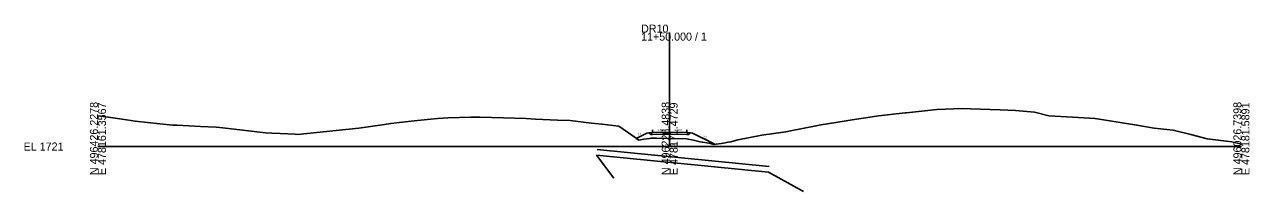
# Model space of a CAD drawing. Extents: x -26 to 403, y -10 to 2062.
# Drawn here: x -25.7 to 402.8, y 1484.3 to 1542.7 of the extents above; entities that cross this region are included whole.
import ezdxf

# ---------------------------------------------------------------- set-up
doc = ezdxf.new("R2010")
doc.units = 0
for name, color, linetype in [('Exist Cross Section Cell', 7, 'Continuous'), ('Exist XS Center Line Elevation Label', 7, 'Continuous'), ('Exist XS Ground Line', 7, 'Continuous'), ('Prop XS Dump Level', 7, 'Continuous'), ('Prop XS Earthwork Shape', 7, 'Continuous'), ('Prop XS EOT Tick Mark', 7, 'Continuous'), ('Prop XS Finish Grade', 7, 'Continuous'), ('Prop XS Finish Grade Earthwork', 7, 'Continuous'), ('Prop XS Finish Grade Pavement', 7, 'Continuous'), ('Prop XS Pvmt Edge Slope', 7, 'Continuous'), ('Prop XS SE Text', 7, 'Continuous'), ('Prop XS Shoulder Borrow Shape', 7, 'Continuous'), ('Prop XS Side Slope Text', 7, 'Continuous'), ('Prop XS Subgrade Earthwork', 7, 'Continuous'), ('Scratch_Level_5', 7, 'Continuous'), ('Scratch_Level_9', 7, 'Continuous')]:
    doc.layers.add(name, color=color, linetype=linetype)

msp = doc.modelspace()

# ---------------------------------------------------------------- linework, layer by layer
at = {"layer": 'Exist Cross Section Cell'}
for p, q in [((200, 1500), (200, 1539.86)), ((0, 1500), (200, 1500)), ((200, 1500), (400, 1500))]:
    msp.add_line(p, q, dxfattribs=at)
at = {"layer": 'Exist XS Ground Line'}
msp.add_lwpolyline([(0, 1510.79), (2.76, 1510.38), (8.44, 1509.55), (13.04, 1508.93), (21.7, 1507.93), (26.15, 1507.53), (27.71, 1507.42), (35.91, 1507.05), (41.41, 1506.75), (42.62, 1506.65), (56.67, 1504.97), (58.67, 1504.77), (60.82, 1504.72), (63.73, 1504.58), (68.95, 1504.33), (69.8, 1504.26), (83.31, 1505.55), (91.28, 1506.39), (100.24, 1507.69), (102.5, 1508.07), (110.61, 1508.99), (118.79, 1509.78), (122.39, 1510.06), (130.46, 1510.25), (133.63, 1510.25), (141.88, 1510.06), (149.65, 1509.75), (153.05, 1509.63), (160.78, 1509.27), (165.2, 1509.08), (172.63, 1508.2), (176.25, 1507.82), (182.27, 1507.16), (188.28, 1502.87), (189.27, 1502.24), (191.01, 1502.54), (192.97, 1502.8), (193.51, 1502.87), (195.4, 1502.88), (200, 1502.78), (205.84, 1502.65), (208.39, 1502.18), (210.72, 1501.61), (213.87, 1501.13), (215.45, 1500.76), (218.86, 1501.21), (220.45, 1501.54), (221.37, 1501.68), (223.83, 1502.29), (232.29, 1503.98), (240.66, 1505.18), (242.3, 1505.44), (251.21, 1507.29), (252.32, 1507.5), (261.76, 1508.98), (262.33, 1509.1), (272.35, 1510.68), (273.05, 1510.76), (282.36, 1511.76), (282.86, 1511.8), (292.38, 1512.88), (293.41, 1512.95), (302.39, 1513.29), (305.21, 1513.18), (315.63, 1512.85), (320.99, 1512.63), (327.6, 1512.06), (332.65, 1510.74), (340.94, 1510.33), (348.82, 1509.8), (355.4, 1508.78), (362.69, 1507.63), (369.52, 1506.46), (376.14, 1505.67), (382.31, 1504.2), (388.04, 1502.73), (396.65, 1501.66), (400, 1500.78)], dxfattribs=at)
at = {"layer": 'Prop XS Dump Level'}
for p, q in [((200, 1504.97), (194, 1504.85)), ((206, 1504.85), (200, 1504.97))]:
    msp.add_line(p, q, dxfattribs=at)
at = {"layer": 'Prop XS Earthwork Shape'}
msp.add_lwpolyline([(200, 1504.3), (194, 1504.18), (193.32, 1504.17), (192.74, 1504.75), (192, 1504.69), (188.32, 1502.85), (189.27, 1502.24), (191.01, 1502.54), (192.97, 1502.8), (193.51, 1502.87), (195.4, 1502.88), (200, 1502.78), (205.84, 1502.65), (208.39, 1502.18), (210.72, 1501.61), (213.87, 1501.13), (215.45, 1500.76), (215.77, 1500.8), (208, 1504.69), (207.26, 1504.75), (206.68, 1504.17), (206, 1504.18)], close=True, dxfattribs=at)
at = {"layer": 'Prop XS EOT Tick Mark'}
for p, q in [((194, 1504.85), (194, 1505.85)), ((206, 1504.85), (206, 1505.85))]:
    msp.add_line(p, q, dxfattribs=at)
at = {"layer": 'Prop XS Finish Grade'}
for p, q in [((194, 1504.85), (192.74, 1504.75)), ((206, 1504.85), (207.26, 1504.75))]:
    msp.add_line(p, q, dxfattribs=at)
at = {"layer": 'Prop XS Finish Grade Earthwork'}
for p, q in [((192, 1504.69), (188.32, 1502.85)), ((192.74, 1504.75), (192, 1504.69)), ((207.26, 1504.75), (208, 1504.69)), ((208, 1504.69), (215.77, 1500.8))]:
    msp.add_line(p, q, dxfattribs=at)
at = {"layer": 'Prop XS Finish Grade Pavement'}
for p, q in [((194, 1504.85), (200, 1504.97)), ((200, 1504.97), (206, 1504.85))]:
    msp.add_line(p, q, dxfattribs=at)
at = {"layer": 'Prop XS Pvmt Edge Slope'}
for p, q in [((194, 1504.85), (193.32, 1504.17)), ((206, 1504.85), (206.68, 1504.17))]:
    msp.add_line(p, q, dxfattribs=at)
at = {"layer": 'Prop XS Shoulder Borrow Shape'}
for points in [[(194, 1504.85), (193.32, 1504.17), (192.74, 1504.75)], [(206.68, 1504.17), (207.26, 1504.75), (206, 1504.85)]]:
    msp.add_lwpolyline(points, close=True, dxfattribs=at)
at = {"layer": 'Prop XS Subgrade Earthwork'}
for p, q in [((193.32, 1504.17), (192.74, 1504.75)), ((194, 1504.18), (193.32, 1504.17)), ((200, 1504.3), (194, 1504.18)), ((206, 1504.18), (200, 1504.3)), ((206, 1504.18), (206.68, 1504.17)), ((206.68, 1504.17), (207.26, 1504.75))]:
    msp.add_line(p, q, dxfattribs=at)
at = {"layer": 'Scratch_Level_5'}
msp.add_lwpolyline([(0, 1510.79), (2.76, 1510.38), (8.44, 1509.55), (13.04, 1508.93), (21.7, 1507.93), (26.15, 1507.53), (27.71, 1507.42), (35.91, 1507.05), (41.41, 1506.75), (42.62, 1506.65), (56.67, 1504.97), (58.67, 1504.77), (60.82, 1504.72), (63.73, 1504.58), (68.95, 1504.33), (69.8, 1504.26), (83.31, 1505.55), (91.28, 1506.39), (100.24, 1507.69), (102.5, 1508.07), (110.61, 1508.99), (118.79, 1509.78), (122.39, 1510.06), (130.46, 1510.25), (133.63, 1510.25), (141.88, 1510.06), (149.65, 1509.75), (153.05, 1509.63), (160.78, 1509.27), (165.2, 1509.08), (172.63, 1508.2), (176.25, 1507.82), (182.27, 1507.16), (188.28, 1502.87), (189.27, 1502.24), (191.01, 1502.54), (192.97, 1502.8), (193.51, 1502.87), (195.4, 1502.88), (200, 1502.78), (205.84, 1502.65), (208.39, 1502.18), (210.72, 1501.61), (213.87, 1501.13), (215.45, 1500.76), (218.86, 1501.21), (220.45, 1501.54), (221.37, 1501.68), (223.83, 1502.29), (232.29, 1503.98), (240.66, 1505.18), (242.3, 1505.44), (251.21, 1507.29), (252.32, 1507.5), (261.76, 1508.98), (262.33, 1509.1), (272.35, 1510.68), (273.05, 1510.76), (282.36, 1511.76), (282.86, 1511.8), (292.38, 1512.88), (293.41, 1512.95), (302.39, 1513.29), (305.21, 1513.18), (315.63, 1512.85), (320.99, 1512.63), (327.6, 1512.06), (332.65, 1510.74), (340.94, 1510.33), (348.82, 1509.8), (355.4, 1508.78), (362.69, 1507.63), (369.52, 1506.46), (376.14, 1505.67), (382.31, 1504.2), (388.04, 1502.73), (396.65, 1501.66), (400, 1500.78)], dxfattribs=at)
at = {"layer": 'Scratch_Level_9'}
for p, q in [((174.43, 1497), (180.49, 1488.97)), ((174.43, 1497), (234.6, 1491)), ((174.63, 1498.99), (234.8, 1492.99)), ((234.6, 1491), (246.77, 1484.25))]:
    msp.add_line(p, q, dxfattribs=at)

# ---------------------------------------------------------------- texts
at = {"layer": 'Exist Cross Section Cell'}
for s, p in [('11+50.000 / 1', (190, 1537.06)), ('DR10', (190, 1539.86)), ('EL 1721', (-26, 1498.6))]:
    msp.add_text(s, height=2.8, dxfattribs=at).set_placement(p)
for s, p in [('N 496426.2278', (0, 1490)), ('E 478161.3567', (2.8, 1490)), ('N 496226.4838', (200, 1490)), ('E 478171.4729', (202.8, 1490)), ('N 496026.7398', (400, 1490)), ('E 478181.5891', (402.8, 1490))]:
    msp.add_text(s, height=2.8, rotation=90, dxfattribs=at).set_placement(p)
at = {"layer": 'Exist XS Center Line Elevation Label'}
msp.add_text('1723.78', height=0.75, dxfattribs=at).set_placement((198.24, 1500.03))
at = {"layer": 'Prop XS Dump Level'}
for p in [(192, 1504.65), (208, 1504.65)]:
    msp.add_text('Case1', height=0.04, dxfattribs=at).set_placement(p)
at = {"layer": 'Prop XS SE Text'}
for rotation, p in [(1.1458, (195.71, 1505.38)), (358.8542, (201.71, 1505.43))]:
    msp.add_text('0.020', height=0.75, rotation=rotation, dxfattribs=at).set_placement(p)
at = {"layer": 'Prop XS Side Slope Text'}
for rotation, p in [(26.5651, (188.85, 1503.75)), (333.4349, (211.63, 1503.27))]:
    msp.add_text('2:1', height=0.75, rotation=rotation, dxfattribs=at).set_placement(p)

doc.saveas('drawing.dxf')
